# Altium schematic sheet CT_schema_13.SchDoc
size 147 x 119 mm
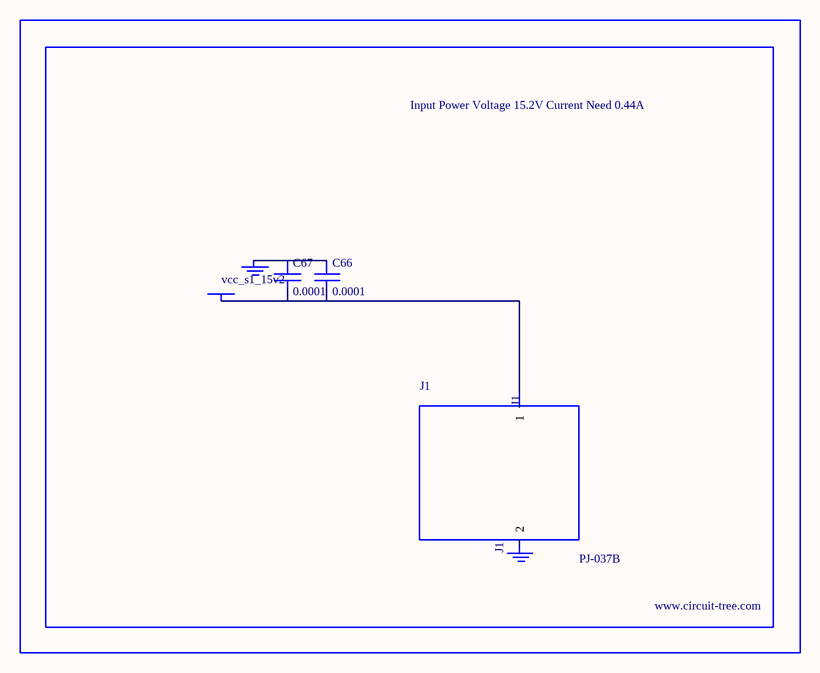
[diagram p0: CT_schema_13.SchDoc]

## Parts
BORDER12  (no value)
C66  0.0001  [EXV-9H]
C67  0.0001  [EXV-9H]
GND_INSTANCE_12_0  (no value)
GND_INSTANCE_12_1  (no value)
J1  PJ-037B  [PJ-037B_PACKAGE]
POWER_INSTANCE_12_0  vcc_s1_15v2

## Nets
NetC66_1: C66.1 C67.1 GND_INSTANCE_12_0.0(GND)
NetC66_2: C66.2 C67.2 J1.1 POWER_INSTANCE_12_0.0(PWR)

Not connected (* = marked no-connect by the designer): GND_INSTANCE_12_1 0(GND); J1 2

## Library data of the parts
BORDER12 = BORDER_PAGE12
C66 C67 = EDK107M035A9HAA
GND_INSTANCE_12_0 GND_INSTANCE_12_1 = GND
POWER_INSTANCE_12_0 = PWR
